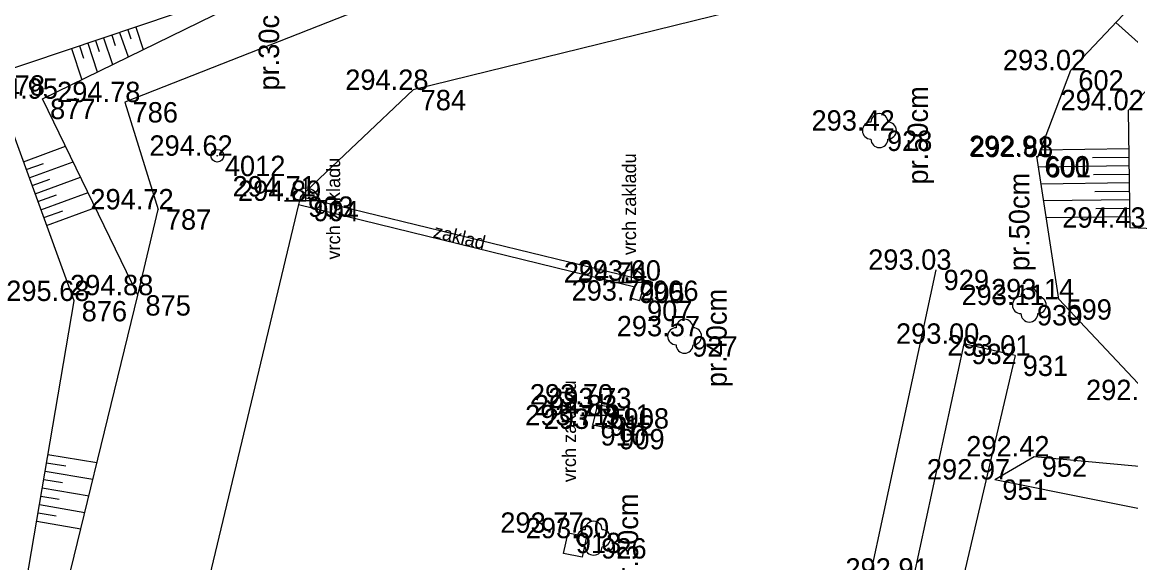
# Model space of a CAD drawing. Extents: x -599970 to -599524, y -1154772 to -1154457.
# Drawn here: x -599765.66 to -599732.99, y -1154635.85 to -1154619.91 of the extents above; entities that cross this region are included whole.
import ezdxf

# ---------------------------------------------------------------- set-up
doc = ezdxf.new("R2010")
doc.units = 0
for name, color, linetype in [('Z-PEVNE BODY-CISLO', 7, 'Continuous'), ('Z-PEVNE BODY-VYSKA', 7, 'Continuous'), ('Z-PEVNE BODY-ZNACKA', 7, 'Continuous'), ('Z-PLOT DRATENY', 7, 'Continuous'), ('Z-PODROBNE BODY', 7, 'Continuous'), ('Z-PODROBNE BODY-CISLO', 7, 'Continuous'), ('Z-PODROBNE BODY-VYSKA', 7, 'Continuous'), ('Z-POPISY OBJEKTU A ZPEVNENYCH PLOCH', 7, 'Continuous'), ('Z-PRUMERY KMENU STROMU', 7, 'Continuous'), ('Z-SRAFOVANI SVAHU', 7, 'Continuous'), ('Z-STROMY ZNACKY KULTUR', 7, 'Continuous'), ('Z-TERENNI HRANY PATY', 7, 'Continuous'), ('Z-VYSKOVE BODY', 7, 'Continuous'), ('Z-ZPEVNENE PLOCHY', 7, 'Continuous')]:
    doc.layers.add(name, color=color, linetype=linetype)

msp = doc.modelspace()

# ---------------------------------------------------------------- linework, layer by layer
at = {"layer": 'Z-PEVNE BODY-ZNACKA'}
for radius in [0.188, 0.188, 0.00896, 0.00896]:
    msp.add_circle((-599759.91, -1154623.85), radius, dxfattribs=at)
at = {"layer": 'Z-PLOT DRATENY'}
msp.add_lwpolyline([(-599745.65, -1154656.68), (-599742.21, -1154643.42), (-599738.73, -1154627.21)], dxfattribs=at)
at = {"layer": 'Z-PODROBNE BODY'}
for p, q in [((-599734.76, -1154621.33), (-599734.76, -1154621.33)), ((-599754.14, -1154621.91), (-599754.14, -1154621.91)), ((-599765.06, -1154622.17), (-599765.06, -1154622.17)), ((-599762.63, -1154622.27), (-599762.63, -1154622.27)), ((-599733.06, -1154622.51), (-599733.06, -1154622.51)), ((-599740.4, -1154623.11), (-599740.4, -1154623.11)), ((-599735.76, -1154623.86), (-599735.76, -1154623.86)), ((-599735.73, -1154623.89), (-599735.73, -1154623.89)), ((-599757.46, -1154625.05), (-599757.46, -1154625.05)), ((-599757.3, -1154625.18), (-599757.3, -1154625.18)), ((-599761.65, -1154625.43), (-599761.65, -1154625.43)), ((-599733.01, -1154625.97), (-599733.01, -1154625.97)), ((-599738.73, -1154627.21), (-599738.73, -1154627.21)), ((-599747.7, -1154627.59), (-599747.7, -1154627.59)), ((-599747.29, -1154627.53), (-599747.29, -1154627.53)), ((-599762.25, -1154627.96), (-599762.25, -1154627.96)), ((-599764.13, -1154628.13), (-599764.13, -1154628.13)), ((-599747.47, -1154628.12), (-599747.47, -1154628.12)), ((-599735.98, -1154628.25), (-599735.98, -1154628.25)), ((-599735.11, -1154628.08), (-599735.11, -1154628.08)), ((-599746.14, -1154629.17), (-599746.14, -1154629.17)), ((-599737.91, -1154629.39), (-599737.91, -1154629.39)), ((-599736.4, -1154629.74), (-599736.4, -1154629.74)), ((-599748.7, -1154631.18), (-599748.7, -1154631.18)), ((-599748.16, -1154631.29), (-599748.16, -1154631.29)), ((-599748.58, -1154631.5), (-599748.58, -1154631.5)), ((-599748.84, -1154631.79), (-599748.84, -1154631.79)), ((-599748.29, -1154631.9), (-599748.29, -1154631.9)), ((-599735.84, -1154632.71), (-599735.84, -1154632.71)), ((-599737, -1154633.39), (-599737, -1154633.39)), ((-599749.57, -1154634.96), (-599749.57, -1154634.96)), ((-599748.82, -1154635.12), (-599748.82, -1154635.12))]:
    msp.add_line(p, q, dxfattribs=at)
at = {"layer": 'Z-SRAFOVANI SVAHU'}
for points in [[(-599762.55, -1154620.14), (-599762.46, -1154620.41)], [(-599762.31, -1154620.06), (-599762.09, -1154620.72)], [(-599731.94, -1154621.26), (-599733.43, -1154619.92)], [(-599763.5, -1154620.45), (-599763.39, -1154620.78)], [(-599763.26, -1154620.38), (-599763, -1154621.16)], [(-599763.02, -1154620.3), (-599762.92, -1154620.6)], [(-599762.79, -1154620.22), (-599762.54, -1154620.94)], [(-599764.21, -1154620.69), (-599763.9, -1154621.61)], [(-599763.97, -1154620.61), (-599763.85, -1154620.97)], [(-599763.73, -1154620.53), (-599763.45, -1154621.38)], [(-599765.62, -1154624.03), (-599764.38, -1154623.57)], [(-599733.04, -1154623.65), (-599735.65, -1154623.69)], [(-599765.54, -1154624.26), (-599765.03, -1154624.08)], [(-599765.45, -1154624.5), (-599764.16, -1154624.03)], [(-599733.04, -1154623.9), (-599734.12, -1154623.91)], [(-599733.04, -1154624.15), (-599735.71, -1154624.19)], [(-599733.03, -1154624.4), (-599734.09, -1154624.41)], [(-599765.37, -1154624.73), (-599764.84, -1154624.54)], [(-599765.28, -1154624.97), (-599763.94, -1154624.48)], [(-599733.03, -1154624.65), (-599735.63, -1154624.69)], [(-599765.2, -1154625.2), (-599764.65, -1154625)], [(-599765.11, -1154625.44), (-599763.72, -1154624.93)], [(-599733.03, -1154624.9), (-599734.05, -1154624.91)], [(-599764.94, -1154625.91), (-599763.5, -1154625.38)], [(-599733.02, -1154625.15), (-599735.56, -1154625.18)], [(-599733.02, -1154625.4), (-599734.02, -1154625.41)], [(-599765.02, -1154625.67), (-599764.46, -1154625.47)], [(-599733.01, -1154625.65), (-599735.48, -1154625.68)], [(-599764.94, -1154632.9), (-599764.37, -1154632.99)], [(-599764.9, -1154632.65), (-599763.46, -1154632.89)], [(-599764.98, -1154633.14), (-599763.58, -1154633.38)], [(-599765.02, -1154633.39), (-599764.47, -1154633.48)], [(-599765.11, -1154633.88), (-599764.57, -1154633.97)], [(-599765.07, -1154633.64), (-599763.69, -1154633.87)], [(-599765.15, -1154634.13), (-599763.81, -1154634.36)], [(-599765.19, -1154634.37), (-599764.66, -1154634.46)], [(-599765.23, -1154634.62), (-599763.93, -1154634.84)]]:
    msp.add_lwpolyline(points, dxfattribs=at)
at = {"layer": 'Z-STROMY ZNACKY KULTUR'}
for centre in [(-599740.4, -1154623.11), (-599735.98, -1154628.25), (-599746.14, -1154629.17), (-599748.82, -1154635.12)]:
    msp.add_circle(centre, 0.00025, dxfattribs=at)
for centre, start, end in [((-599740.4, -1154622.86), 0, 180), ((-599740.65, -1154623.11), 90, 270), ((-599740.15, -1154623.11), 270, 90), ((-599740.4, -1154623.36), 180, 360), ((-599736.23, -1154628.25), 90, 270), ((-599735.98, -1154628), 0, 180), ((-599735.73, -1154628.25), 270, 90), ((-599746.14, -1154628.92), 0, 180), ((-599735.98, -1154628.5), 180, 360), ((-599746.39, -1154629.17), 90, 270), ((-599745.89, -1154629.17), 270, 90), ((-599746.14, -1154629.42), 180, 360), ((-599749.07, -1154635.12), 90, 270), ((-599748.82, -1154634.87), 0, 180), ((-599748.57, -1154635.12), 270, 90), ((-599748.82, -1154635.37), 180, 360)]:
    msp.add_arc(centre, 0.25, start, end, dxfattribs=at)
at = {"layer": 'Z-TERENNI HRANY PATY'}
for points in [[(-599706.85, -1154650.78), (-599713.18, -1154651.03), (-599721.07, -1154652.91), (-599723.76, -1154645.8), (-599725.1, -1154640.23), (-599727.83, -1154634.18), (-599728.54, -1154633), (-599732.31, -1154631.05), (-599735.11, -1154628.08), (-599735.76, -1154623.86), (-599735.73, -1154623.89), (-599734.76, -1154621.33), (-599730.32, -1154616.62), (-599722.93, -1154615.52), (-599713.66, -1154613.52), (-599712.4, -1154614.76), (-599710.05, -1154618.59), (-599710.54, -1154622.05), (-599712.9, -1154623.66), (-599717.25, -1154628.18), (-599716.96, -1154629.04), (-599714.58, -1154631.6), (-599714.4, -1154633.54), (-599711.28, -1154633.06)], [(-599704.68, -1154613.79), (-599704.97, -1154620.78), (-599707.54, -1154629.53), (-599708.11, -1154633.78), (-599709.03, -1154641.46), (-599708.95, -1154648.47), (-599720.11, -1154645.96), (-599722.14, -1154639.54), (-599721.91, -1154632.94), (-599724.31, -1154631.24), (-599726.05, -1154627.36), (-599728.73, -1154626.15), (-599733.01, -1154625.97), (-599733.06, -1154622.51), (-599729.32, -1154618.34), (-599722.3, -1154617.17), (-599714.17, -1154615.37), (-599711.22, -1154619.52), (-599712.8, -1154621.32)], [(-599760.06, -1154619.3), (-599760.06, -1154618.64), (-599762.33, -1154616.65), (-599765, -1154617.66), (-599767.23, -1154619.14), (-599772.56, -1154623.16), (-599769.35, -1154628.39), (-599766.8, -1154637.11), (-599765.7, -1154637.36), (-599764.13, -1154628.13), (-599766.55, -1154621.48), (-599760.06, -1154619.3)], [(-599762.25, -1154627.96), (-599765.06, -1154622.17), (-599759.17, -1154619.3)], [(-599737, -1154633.39), (-599735.84, -1154632.71), (-599729.01, -1154633.34)], [(-599737, -1154633.39), (-599728.04, -1154635.19), (-599729.88, -1154642.45), (-599730.13, -1154644.4), (-599731.9, -1154653.11)]]:
    msp.add_lwpolyline(points, dxfattribs=at)
at = {"layer": 'Z-VYSKOVE BODY'}
for p, q in [((-599757.3, -1154624.555), (-599757.3, -1154624.805)), ((-599757.3, -1154624.805), (-599757.3, -1154624.555)), ((-599757.3, -1154625.18), (-599757.3, -1154624.555)), ((-599757.3, -1154624.555), (-599757.3, -1154624.805)), ((-599756.675, -1154625.18), (-599757.925, -1154625.18)), ((-599757.925, -1154625.18), (-599757.3, -1154625.18)), ((-599756.675, -1154625.18), (-599757.3, -1154625.18)), ((-599747.7, -1154626.965), (-599747.7, -1154627.215)), ((-599747.7, -1154627.215), (-599747.7, -1154626.965)), ((-599747.7, -1154627.59), (-599747.7, -1154626.965)), ((-599747.7, -1154626.965), (-599747.7, -1154627.215)), ((-599747.075, -1154627.59), (-599748.325, -1154627.59)), ((-599748.325, -1154627.59), (-599747.7, -1154627.59)), ((-599747.075, -1154627.59), (-599747.7, -1154627.59)), ((-599748.58, -1154630.875), (-599748.58, -1154631.125)), ((-599748.58, -1154631.125), (-599748.58, -1154630.875)), ((-599748.58, -1154631.5), (-599748.58, -1154630.875)), ((-599748.58, -1154630.875), (-599748.58, -1154631.125)), ((-599747.955, -1154631.5), (-599749.205, -1154631.5)), ((-599749.205, -1154631.5), (-599748.58, -1154631.5)), ((-599747.955, -1154631.5), (-599748.58, -1154631.5))]:
    msp.add_line(p, q, dxfattribs=at)
for centre, start, end in [((-599757.3, -1154625.18), 90, 180), ((-599757.3, -1154625.18), 0, 90), ((-599747.7, -1154627.59), 90, 180), ((-599747.7, -1154627.59), 0, 90), ((-599748.58, -1154631.5), 90, 180), ((-599748.58, -1154631.5), 0, 90)]:
    msp.add_arc(centre, 0.375, start, end, dxfattribs=at)
at = {"layer": 'Z-ZPEVNENE PLOCHY'}
for points in [[(-599671.02, -1154617.03), (-599671.63, -1154613.35), (-599675.05, -1154613.45), (-599680.32, -1154612.41), (-599686.62, -1154610.91), (-599694.45, -1154609.33), (-599700.34, -1154608.57), (-599705.79, -1154608.71), (-599715.78, -1154610.69), (-599725.58, -1154612.61), (-599730.02, -1154613.49), (-599735.64, -1154614.56), (-599743.95, -1154616.26), (-599754.96, -1154619.25), (-599762.63, -1154622.27), (-599761.65, -1154625.43)], [(-599671.02, -1154617.03), (-599674, -1154617.11), (-599674.74, -1154618.09), (-599672.97, -1154619.61), (-599672.99, -1154619.63), (-599673.43, -1154624.97), (-599672.1, -1154632.73), (-599679.37, -1154632.4), (-599679.21, -1154625.35), (-599679.14, -1154619.7), (-599679.61, -1154616.32), (-599687.06, -1154613.66), (-599695, -1154612.23), (-599700.47, -1154611.47), (-599705.51, -1154611.86), (-599715.16, -1154613.61), (-599724.96, -1154615.5), (-599735.23, -1154617.18), (-599743.14, -1154619.2), (-599754.14, -1154621.91)], [(-599754.14, -1154621.91), (-599757.46, -1154625.05), (-599757.52, -1154625.29), (-599760.31, -1154636.94), (-599763.2, -1154648.7), (-599766.8, -1154663.87), (-599769.11, -1154662.8), (-599767.23, -1154647.84), (-599764.82, -1154638.47), (-599762.25, -1154627.96), (-599761.65, -1154625.43)], [(-599757.46, -1154625.05), (-599747.29, -1154627.53), (-599747.47, -1154628.12)], [(-599757.52, -1154625.29), (-599747.61, -1154627.71), (-599747.71, -1154628.05), (-599747.47, -1154628.12)], [(-599736.4, -1154629.74), (-599737.91, -1154629.39), (-599739.4, -1154636.31), (-599741.02, -1154644.12), (-599743.78, -1154656.73), (-599742.17, -1154657.08)], [(-599736.4, -1154629.74), (-599737.98, -1154636.49), (-599739.47, -1154644.6), (-599742.17, -1154657.08)], [(-599748.16, -1154631.29), (-599748.29, -1154631.9), (-599748.84, -1154631.79), (-599748.7, -1154631.18), (-599748.16, -1154631.29)], [(-599749.03, -1154635.07), (-599749.16, -1154635.68), (-599749.71, -1154635.57), (-599749.57, -1154634.96), (-599749.03, -1154635.07)]]:
    msp.add_lwpolyline(points, dxfattribs=at)

# ---------------------------------------------------------------- texts
at = {"layer": 'Z-PEVNE BODY-CISLO'}
msp.add_text(' 4012', height=0.6, dxfattribs=at).set_placement((-599759.91, -1154624.45))
at = {"layer": 'Z-PEVNE BODY-VYSKA'}
msp.add_text('294.62 ', height=0.6, dxfattribs=at).set_placement((-599761.91, -1154623.85))
at = {"layer": 'Z-PODROBNE BODY-CISLO'}
for s, p in [(' 878', (-599766.55, -1154622.08)), (' 602', (-599734.76, -1154621.93)), (' 784', (-599754.14, -1154622.51)), (' 877', (-599765.06, -1154622.77)), (' 786', (-599762.63, -1154622.87)), (' 928', (-599740.4, -1154623.71)), (' 600', (-599735.76, -1154624.46)), (' 601', (-599735.73, -1154624.49)), (' 903', (-599757.46, -1154625.65)), (' 787', (-599761.65, -1154626.03)), (' 904', (-599757.3, -1154625.78)), (' 929', (-599738.73, -1154627.81)), (' 905', (-599747.7, -1154628.19)), (' 906', (-599747.29, -1154628.13)), (' 875', (-599762.25, -1154628.56)), (' 876', (-599764.13, -1154628.73)), (' 907', (-599747.47, -1154628.72)), (' 930', (-599735.98, -1154628.85)), (' 599', (-599735.11, -1154628.68)), (' 927', (-599746.14, -1154629.77)), (' 932', (-599737.91, -1154629.99)), (' 931', (-599736.4, -1154630.34)), (' 911', (-599748.7, -1154631.78)), (' 908', (-599748.16, -1154631.89)), (' 912', (-599748.58, -1154632.1)), (' 910', (-599748.84, -1154632.39)), (' 909', (-599748.29, -1154632.5)), (' 952', (-599735.84, -1154633.31)), (' 951', (-599737, -1154633.99)), (' 913', (-599749.57, -1154635.56)), (' 926', (-599748.82, -1154635.72))]:
    msp.add_text(s, height=0.6, dxfattribs=at).set_placement(p)
at = {"layer": 'Z-PODROBNE BODY-VYSKA'}
for s, p in [('293.02 ', (-599736.76, -1154621.33)), ('294.28 ', (-599756.14, -1154621.91)), ('294.95 ', (-599767.06, -1154622.17)), ('294.78 ', (-599764.63, -1154622.27)), ('294.02 ', (-599735.06, -1154622.51)), ('293.42 ', (-599742.4, -1154623.11)), ('292.91 ', (-599737.76, -1154623.86)), ('292.88 ', (-599737.73, -1154623.89)), ('294.71 ', (-599759.46, -1154625.05)), ('294.89 ', (-599759.3, -1154625.18)), ('294.72 ', (-599763.65, -1154625.43)), ('294.43 ', (-599735.01, -1154625.97)), ('293.03 ', (-599740.73, -1154627.21)), ('294.74 ', (-599749.7, -1154627.59)), ('293.60 ', (-599749.29, -1154627.53)), ('294.88 ', (-599764.25, -1154627.96)), ('295.68 ', (-599766.13, -1154628.13)), ('293.72 ', (-599749.47, -1154628.12)), ('293.11 ', (-599737.98, -1154628.25)), ('293.14 ', (-599737.11, -1154628.08)), ('293.57 ', (-599748.14, -1154629.17)), ('293.00 ', (-599739.91, -1154629.39)), ('293.01 ', (-599738.4, -1154629.74)), ('293.70 ', (-599750.7, -1154631.18)), ('292.48 ', (-599734.31, -1154631.05)), ('294.83 ', (-599750.58, -1154631.5)), ('293.73 ', (-599750.16, -1154631.29)), ('293.71 ', (-599750.84, -1154631.79)), ('293.75 ', (-599750.29, -1154631.9)), ('292.42 ', (-599737.84, -1154632.71)), ('292.97 ', (-599739, -1154633.39)), ('293.77 ', (-599751.57, -1154634.96)), ('293.60 ', (-599750.82, -1154635.12)), ('292.91 ', (-599741.4, -1154636.31))]:
    msp.add_text(s, height=0.6, dxfattribs=at).set_placement(p)
at = {"layer": 'Z-POPISY OBJEKTU A ZPEVNENYCH PLOCH'}
msp.add_text('zaklad', height=0.4, rotation=346.2956, dxfattribs=at).set_placement((-599753.57, -1154626.25))
at = {"layer": 'Z-PRUMERY KMENU STROMU'}
for s, p in [('pr.30cm', (-599758.09, -1154621.93)), ('pr.50cm', (-599738.97, -1154624.7)), ('pr.50cm', (-599735.98, -1154627.25)), ('pr.40cm', (-599744.9, -1154630.67)), ('pr.30cm', (-599747.51, -1154636.7))]:
    msp.add_text(s, height=0.6, rotation=90, dxfattribs=at).set_placement(p)
at = {"layer": 'Z-VYSKOVE BODY'}
for p in [(-599756.29, -1154626.91), (-599747.57, -1154626.78), (-599749.34, -1154633.47)]:
    msp.add_text('vrch zakladu', height=0.4, rotation=90, dxfattribs=at).set_placement(p)

doc.saveas('drawing.dxf')
